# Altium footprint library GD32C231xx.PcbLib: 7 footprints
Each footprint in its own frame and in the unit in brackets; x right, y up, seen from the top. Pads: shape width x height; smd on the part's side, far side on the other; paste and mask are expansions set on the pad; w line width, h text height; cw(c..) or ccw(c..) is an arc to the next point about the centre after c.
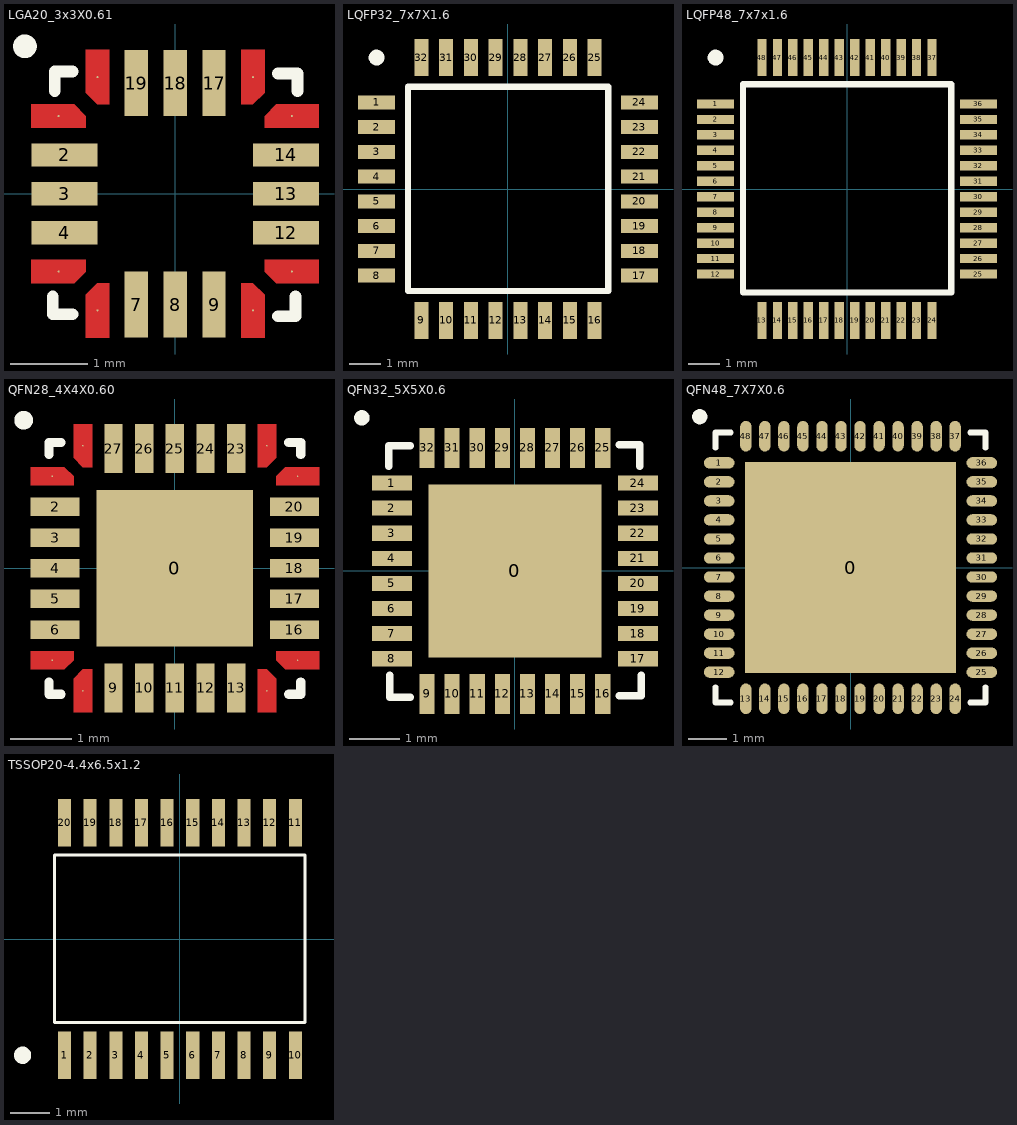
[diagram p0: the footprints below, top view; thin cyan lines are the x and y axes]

## LGA20_3x3X0.61 [mm]
pads (20):
  round 0.025 smd mask+0.102: 1(-1.5,1)
  rect 0.85x0.3 smd: 2(-1.425,0.5) 3(-1.425,0) 4(-1.425,-0.5) 12(1.425,-0.5) 13(1.425,0) 14(1.425,0.5)
  round 0.025 smd: 5(-1.5,-1) 6(-1,-1.5) 10(1,-1.5) 11(1.5,-1) 15(1.5,1) 16(1,1.5) 20(-1,1.5)
  rect 0.3x0.85 smd: 7(-0.5,-1.425) 8(0,-1.425) 9(0.5,-1.425) 17(0.5,1.425) 18(0,1.425) 19(-0.5,1.425)
Top Layer:
  region: -1.15,-1.85 -1.15,-1.3 -1,-1.15 -0.85,-1.15 -0.85,-1.85
  region: 0.85,-1.85 1.15,-1.85 1.15,-1.3 1,-1.15 0.85,-1.15
  region: 1.15,-1 1.3,-1.15 1.85,-1.15 1.85,-0.85 1.15,-0.85
  region: -1.15,1.3 -1.15,1.85 -0.85,1.85 -0.85,1.15 -1,1.15
  region: -1.85,0.85 -1.85,1.15 -1.3,1.15 -1.15,1 -1.15,0.85
  region: -1.85,-1.15 -1.85,-0.85 -1.15,-0.85 -1.15,-1 -1.3,-1.15
  region: 0.85,1.15 1,1.15 1.15,1.3 1.15,1.85 0.85,1.85
  region: 1.15,0.85 1.15,1 1.3,1.15 1.85,1.15 1.85,0.85
Top Overlay:
  circle w0.152: c-1.933,1.897 r0.076
  lines w0.152: -1.576,-1.321 -1.576,-1.549 -1.322,-1.549 ; -1.549,1.321 -1.549,1.575 -1.32,1.575 ; 1.321,-1.576 1.549,-1.576 1.549,-1.322 ; 1.322,1.549 1.576,1.549 1.576,1.321
3D body "LGA20_3x3X0.61.STEP": height 0.59, standoff -0.02, extent -1.551,-1.551 1.556,1.551

## LQFP32_7x7X1.6 [mm]
pads (32):
  rect 1.2x0.45 smd: 1(-4.25,2.8) 2(-4.25,2) 3(-4.25,1.2) 4(-4.25,0.4) 5(-4.25,-0.4) 6(-4.25,-1.2) 7(-4.25,-2) 8(-4.25,-2.8) 17(4.25,-2.8) 18(4.25,-2) 19(4.25,-1.2) 20(4.25,-0.4) 21(4.25,0.4) 22(4.25,1.2) 23(4.25,2) 24(4.25,2.8)
  rect 0.45x1.2 smd: 9(-2.8,-4.25) 10(-2,-4.25) 11(-1.2,-4.25) 12(-0.4,-4.25) 13(0.4,-4.25) 14(1.2,-4.25) 15(2,-4.25) 16(2.8,-4.25) 25(2.8,4.25) 26(2,4.25) 27(1.2,4.25) 28(0.4,4.25) 29(-0.4,4.25) 30(-1.2,4.25) 31(-2,4.25) 32(-2.8,4.25)
Top Overlay:
  circle w0.254: c-4.25,4.25 r0.127
  lines w0.203: -3.234,-3.296 3.243,-3.296 3.243,3.308 -3.234,3.308 -3.234,-3.296
3D body "TQFP80P900X900X160-32N.step": height 1.6, standoff 0, extent -4.5,-4.5 4.5,4.5

## LQFP48_7x7x1.6 [mm]
pads (48):
  rect 1.2x0.3 smd: 1(-4.25,2.75) 2(-4.25,2.25) 3(-4.25,1.75) 4(-4.25,1.25) 5(-4.25,0.75) 6(-4.25,0.25) 7(-4.25,-0.25) 8(-4.25,-0.75) 9(-4.25,-1.25) 10(-4.25,-1.75) 11(-4.25,-2.25) 12(-4.25,-2.75) 25(4.25,-2.75) 26(4.25,-2.25) 27(4.25,-1.75) 28(4.25,-1.25) 29(4.25,-0.75) 30(4.25,-0.25) 31(4.25,0.25) 32(4.25,0.75) 33(4.25,1.25) 34(4.25,1.75) 35(4.25,2.25) 36(4.25,2.75)
  rect 0.3x1.2 smd: 13(-2.75,-4.25) 14(-2.25,-4.25) 15(-1.75,-4.25) 16(-1.25,-4.25) 17(-0.75,-4.25) 18(-0.25,-4.25) 19(0.25,-4.25) 20(0.75,-4.25) 21(1.25,-4.25) 22(1.75,-4.25) 23(2.25,-4.25) 24(2.75,-4.25) 37(2.75,4.25) 38(2.25,4.25) 39(1.75,4.25) 40(1.25,4.25) 41(0.75,4.25) 42(0.25,4.25) 43(-0.25,4.25) 44(-0.75,4.25) 45(-1.25,4.25) 46(-1.75,4.25) 47(-2.25,4.25) 48(-2.75,4.25)
Top Overlay:
  circle w0.254: c-4.25,4.25 r0.127
  lines w0.203: -3.361,-3.346 3.37,-3.346 3.37,3.385 -3.361,3.385 -3.361,-3.346
3D body "TSQFP50P900X900X160-48N.step": height 1.6, standoff 0, extent -4.5,-4.5 4.5,4.5

## QFN28_4X4X0.60 [mm]
pads (29):
  rect 2.55x2.55 smd: 0(0,0)
  round 0.025 smd: 1(-2,1.5) 7(-2,-1.5) 8(-1.5,-2) 14(1.5,-2) 15(2,-1.5) 21(2,1.5) 22(1.5,2) 28(-1.5,2)
  rect 0.8x0.3 smd: 2(-1.95,1) 3(-1.95,0.5) 4(-1.95,0) 5(-1.95,-0.5) 6(-1.95,-1) 16(1.95,-1) 17(1.95,-0.5) 18(1.95,0) 19(1.95,0.5) 20(1.95,1)
  rect 0.3x0.8 smd: 9(-1,-1.95) 10(-0.5,-1.95) 11(0,-1.95) 12(0.5,-1.95) 13(1,-1.95) 23(1,1.95) 24(0.5,1.95) 25(0,1.95) 26(-0.5,1.95) 27(-1,1.95)
Top Layer:
  region: 1.35,2.35 1.65,2.35 1.65,1.8 1.5,1.65 1.35,1.65
  region: 1.8,1.65 1.65,1.5 1.65,1.35 2.35,1.35 2.35,1.65
  region: 2.35,-1.35 2.35,-1.65 1.8,-1.65 1.65,-1.5 1.65,-1.35
  region: 1.65,-1.8 1.5,-1.65 1.35,-1.65 1.35,-2.35 1.65,-2.35
  region: -1.35,-2.35 -1.65,-2.35 -1.65,-1.8 -1.5,-1.65 -1.35,-1.65
  region: -1.8,-1.65 -1.65,-1.5 -1.65,-1.35 -2.35,-1.35 -2.35,-1.65
  region: -2.35,1.35 -2.35,1.65 -1.8,1.65 -1.65,1.5 -1.65,1.35
  region: -1.65,1.8 -1.5,1.65 -1.35,1.65 -1.35,2.35 -1.65,2.35
Top Overlay:
  circle w0.152: c-2.464,2.413 r0.076
  lines w0.152: -2.051,-1.854 -2.051,-2.051 -1.854,-2.051 ; -2.051,1.854 -2.051,2.051 -1.854,2.051 ; 1.854,-2.051 2.051,-2.051 2.051,-1.854 ; 1.854,2.051 2.051,2.051 2.051,1.854
3D body "QFN28_4X4X0.60.STEP": height 0.6, standoff 0, extent -2.051,-2.051 2.051,2.051

## QFN32_5X5X0.6 [mm]
pads (33):
  rect 3.45x3.45 smd: 0(0,0)
  rect 0.8x0.3 smd: 1(-2.45,1.75) 2(-2.45,1.25) 3(-2.45,0.75) 4(-2.45,0.25) 5(-2.45,-0.25) 6(-2.45,-0.75) 7(-2.45,-1.25) 8(-2.45,-1.75) 17(2.45,-1.75) 18(2.45,-1.25) 19(2.45,-0.75) 20(2.45,-0.25) 21(2.45,0.25) 22(2.45,0.75) 23(2.45,1.25) 24(2.45,1.75)
  rect 0.3x0.8 smd: 9(-1.75,-2.45) 10(-1.25,-2.45) 11(-0.75,-2.45) 12(-0.25,-2.45) 13(0.25,-2.45) 14(0.75,-2.45) 15(1.25,-2.45) 16(1.75,-2.45) 25(1.75,2.45) 26(1.25,2.45) 27(0.75,2.45) 28(0.25,2.45) 29(-0.25,2.45) 30(-0.75,2.45) 31(-1.25,2.45) 32(-1.75,2.45)
Top Overlay:
  circle w0.152: c-3.048,3.048 r0.076
  lines w0.152: -2.515,2.083 -2.515,2.489 -2.083,2.489 ; -2.489,-2.083 -2.489,-2.515 -2.083,-2.515 ; 2.083,-2.489 2.515,-2.489 2.515,-2.083 ; 2.083,2.515 2.489,2.515 2.489,2.083
3D body "QFN50P500X500X60_HS-33N.step": height 0.6, standoff 0, extent -2.551,-2.551 2.551,2.551

## QFN48_7X7X0.6 [mm]
pads (49):
  rect 5.55x5.55 smd: 0(0,0)
  oval 0.8x0.3 smd: 1(-3.45,2.75) 2(-3.45,2.25) 3(-3.45,1.75) 4(-3.45,1.25) 5(-3.45,0.75) 6(-3.45,0.25) 7(-3.45,-0.25) 8(-3.45,-0.75) 9(-3.45,-1.25) 10(-3.45,-1.75) 11(-3.45,-2.25) 12(-3.45,-2.75) 25(3.45,-2.75) 26(3.45,-2.25) 27(3.45,-1.75) 28(3.45,-1.25) 29(3.45,-0.75) 30(3.45,-0.25) 31(3.45,0.25) 32(3.45,0.75) 33(3.45,1.25) 34(3.45,1.75) 35(3.45,2.25) 36(3.45,2.75)
  oval 0.3x0.8 smd: 13(-2.75,-3.45) 14(-2.25,-3.45) 15(-1.75,-3.45) 16(-1.25,-3.45) 17(-0.75,-3.45) 18(-0.25,-3.45) 19(0.25,-3.45) 20(0.75,-3.45) 21(1.25,-3.45) 22(1.75,-3.45) 23(2.25,-3.45) 24(2.75,-3.45) 37(2.75,3.45) 38(2.25,3.45) 39(1.75,3.45) 40(1.25,3.45) 41(0.75,3.45) 42(0.25,3.45) 43(-0.25,3.45) 44(-0.75,3.45) 45(-1.25,3.45) 46(-1.75,3.45) 47(-2.25,3.45) 48(-2.75,3.45)
Top Overlay:
  circle w0.254: c-3.962,3.962 r0.072
  lines w0.152: -3.551,-3.15 -3.551,-3.551 -3.15,-3.551 ; -3.551,3.15 -3.551,3.551 -3.15,3.551 ; 3.15,-3.551 3.551,-3.551 3.551,-3.15 ; 3.15,3.551 3.551,3.551 3.551,3.15
3D body "QFN50P700X700X60_HS-49N.step": height 0.6, standoff 0, extent -3.576,-3.551 3.526,3.551

## TSSOP20-4.4x6.5x1.2 [mm]
pads (20):
  rect 0.33x1.2 smd: 1(-2.925,-2.95) 2(-2.275,-2.95) 3(-1.625,-2.95) 4(-0.975,-2.95) 5(-0.325,-2.95) 6(0.325,-2.95) 7(0.975,-2.95) 8(1.625,-2.95) 9(2.275,-2.95) 10(2.925,-2.95) 11(2.925,2.95) 12(2.275,2.95) 13(1.625,2.95) 14(0.975,2.95) 15(0.325,2.95) 16(-0.325,2.95) 17(-0.975,2.95) 18(-1.625,2.95) 19(-2.275,2.95) 20(-2.925,2.95)
Top Overlay:
  circle w0.254: c-3.988,-2.946 r0.092
  lines w0.076: -3.179,-2.112 -3.179,2.13 3.171,2.13 3.171,-2.112 -3.179,-2.112
3D body "TSOP65P640X120-20N.step": height 1.2, standoff 0, extent -3.3,-3.2 3.3,3.2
